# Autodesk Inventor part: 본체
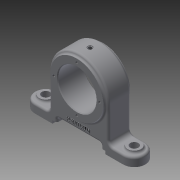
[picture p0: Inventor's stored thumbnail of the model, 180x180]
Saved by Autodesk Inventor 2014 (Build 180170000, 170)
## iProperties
Created: 2019-05
Part Number: 본체
Material: Generic
Document SubType Name: Modeling
Designer: kh
Density: 1 g/cm^3
Appearance: Default
Author: kh
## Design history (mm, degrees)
sketch "Sketch5"
  geometry: L1 (-60, 0)-(60, 0); L2 (-60, -15)-(60, -15); L3 (60, 15)-(-60, 15); A1 r 15 centre (-60, 0) between (-60, 15) and (-60, -15); A2 r 15 centre (60, 0) between (60, -15) and (60, 15); 2 further points
  constraints: 8 end point, 4 point on circle, 4 tangent, 2 centre point, 1 coincident, 1 horizontal, 1 midpoint, 1 parallel
  dimensions: "d35" = 15 radius of A1; "d36" = 120 distance of L1.end L1.start
extrude "Extrusion5" new body sketch "Sketch5" distance "d37" = 12; taper "d38" = 0 deg
sketch "Sketch6"
  geometry: L1 (0, 0)-(0, 60); L2 (60, 12)-(-60, 12) reference; L3 (-40, 60)-(-40, 12); L4 (40, 60)-(40, 12); L5 (40, 12)-(-40, 12); A1 r 40 centre (0, 60) between (-40, 60) and (40, 60)
  constraints: 8 end point, 2 point on circle, 2 point on line, 2 tangent, 1 centre point, 1 coincident, 1 collinear, 1 parallel, 1 perpendicular, 1 vertical
  dimensions: "d39" = 60 distance of L1.start L1.end; "d40" = 80 diameter of A1
extrude "Extrusion6" join sketch "Sketch6" stored distance "d41" = 30; taper "d42" = 0 deg
sketch "Sketch7"
  geometry: C1 r 36 at (60, 60); A1 r 40 centre (60, 60) between (100, 60) and (20, 60) reference; 1 further point
  constraints: 1 centre point, 1 coincident
  dimensions: "d43" = 72 diameter of C1
extrude "Extrusion7" join sketch "Sketch7" distance "d44" = 3; taper "d45" = 0 deg
mirror "Mirror1"
hole "Hole2" diameter "d48" = 52; stored, may be unused: countersink angle "d52" = 90 deg, drill point angle "d54" = 118 deg; dims "d46" = 10, "d47" = 10, "d49" = 6, "d50" = 4, "d51" = 2, "d53" = 8
sketch "Sketch8"
  geometry: L1 (0, 0)-(120, 0) reference; L2 (24, 0)-(24, 4); L3 (24, 4)-(30, 4); L4 (30, 4)-(30, 10); L5 (30, 10)-(90, 10); L6 (90, 10)-(90, 4); L7 (90, 4)-(96, 4); L8 (96, 4)-(96, 0); L9 (24, 0)-(96, 0); 3 further points
  constraints: 16 end point, 4 perpendicular, 3 parallel, 2 equal length, 2 midpoint, 2 point on line, 1 collinear, 1 vertical alignment
  dimensions: "d55" = 60 distance of L4.end L5.end; "d56" = 72 distance between parallel lines of L2 L8; "d57" = 10 distance from line of L2.start L5; "d58" = 4 distance of L2.start L2.end
extrude "Extrusion8" cut sketch "Sketch8" stored distance "d59" = 3; taper "d60" = 0 deg
workplane "Work Plane1"
sketch "Sketch9"
  geometry: L1 (-40, -15)-(-40, 15) reference; L2 (-40, 15)-(-60, 15) reference; L3 (-60, -15)-(-40, -15) reference; C1 r 9 at (-60, 0); C2 r 9 at (60, 0); A1 r 15 centre (-60, 0) between (-60, 15) and (-60, -15) reference; A2 r 15 centre (60, 0) between (60, -15) and (60, 15) reference; 1 further point
  constraints: 2 centre point, 2 coincident
  dimensions: "d62" = 18 diameter of C1; "d63" = 18 diameter of C2
extrude "Extrusion9" join sketch "Sketch9" stored distance "d64" = 3; taper "d65" = 0 deg
sketch "Sketch10"
  geometry: C1 r 9 at (0, 0) reference; C2 r 9 at (120, 0) reference; 1 further point
hole "Hole3" sketch "Sketch10" at (0, 0), (120, 0) diameter "d66" = 11; stored, may be unused: countersink angle "d70" = 90 deg, drill point angle "d72" = 118 deg; dims "d67" = 6, "d68" = 4, "d69" = 2, "d71" = 8
sketch "Sketch11"
  geometry: L1 (0, 0)-(0, 31); C1 r 26 at (0, 0) reference; 2 further points
  constraints: 2 end point, 1 coincident, 1 vertical
  dimensions: "d73" = 31 distance of L1.start L1.end
hole "Hole4" sketch "Sketch11" at (0, 31) diameter "d74" = 3.242; stored, may be unused: countersink angle "d78" = 90 deg, drill point angle "d80" = 118 deg; dims "d75" = 6, "d76" = 4, "d77" = 2, "d79" = 8
pattern_circular "Circular Pattern1" dims angle "d82" = 360 deg
mirror "Mirror2"
workplane "Work Plane2"
sketch "Sketch12"
  geometry: 2 further points
  constraints: 1 coincident
hole "Hole5" sketch "Sketch12" at (0, 0) diameter "d85" = 5.134; stored, may be unused: countersink angle "d89" = 90 deg, drill point angle "d91" = 0 deg; dims "d86" = 8, "d87" = 7, "d88" = 1, "d90" = 10
sketch "Sketch13"
  geometry: 2 further points
  constraints: 1 coincident
hole "Hole6" sketch "Sketch13" at (0, 0) diameter "d92" = 2; stored, may be unused: countersink angle "d96" = 120 deg, drill point angle "d98" = 0 deg; dims "d93" = 9, "d94" = 5.13, "d95" = 1, "d97" = 10
sketch "Sketch14"
  geometry: 3 further points
  constraints: 2 vertical alignment, 1 other
hole "Hole7" sketch "Sketch14" at (0, 26) diameter "d99" = 3; stored, may be unused: countersink angle "d103" = 82 deg, drill point angle "d105" = 0 deg; dims "d100" = 9, "d101" = 6, "d102" = 1, "d104" = 10
fillet "Fillet1" dims "d106" = 6
chamfer "Chamfer1" distance "d107" = 1; stored, may be unused: second distance "d108" = 2, angle "d109" = 45 deg
fillet "Fillet3" dims "d111" = 3
fillet "Fillet4" dims "d112" = 3
fillet "Fillet5" dims "d113" = 3
fillet "Fillet6" dims "d114" = 3
fillet "Fillet7" dims "d115" = 3
sketch "Sketch15"
  geometry: L1 (43.408, 19.402)-(76.592, 19.402); L2 (76.592, 19.402)-(76.592, 14.598); L3 (76.592, 14.598)-(43.408, 14.598); L4 (43.408, 14.598)-(43.408, 19.402); L5 (43.408, 19.402)-(76.592, 14.598); L6 (33, 10)-(87, 10) reference; 2 further points
  constraints: 2 end point, 1 midpoint, 1 vertical alignment, 2 other
  dimensions: "d116" = 7 distance from line of L6 point (60, 17)
emboss "Emboss1" sketch "Sketch15" dims "d35" = 15, "d36" = 120, "d117" = 0.5, "d118" = 0
body "Solid2"
node "Projected Loop1"
other parameters: "d61" = 15
